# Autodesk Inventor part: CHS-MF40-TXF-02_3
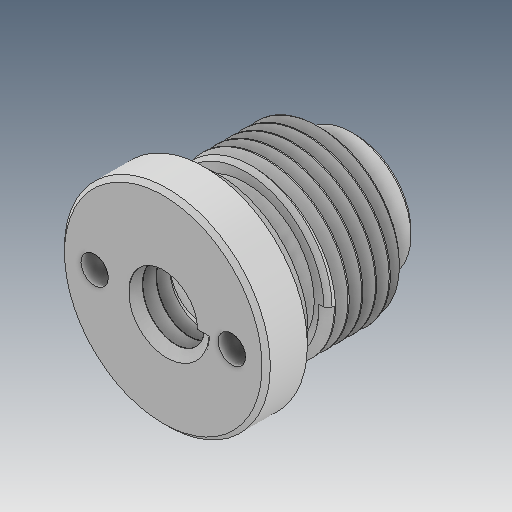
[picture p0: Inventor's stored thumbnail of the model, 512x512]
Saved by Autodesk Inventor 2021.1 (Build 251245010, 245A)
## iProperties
Created: 2019-05
Part Number: CHS-MF40-TXF-02_3
Material: Ogólny
Document SubType Name: Modeling
Designer: user
Density: 1 g/cm^3
Appearance: Domyślna
Author: user
Revision Number: ÈÎºÎ
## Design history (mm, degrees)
feature "ÊäÈë1"
node "Bryła1"
